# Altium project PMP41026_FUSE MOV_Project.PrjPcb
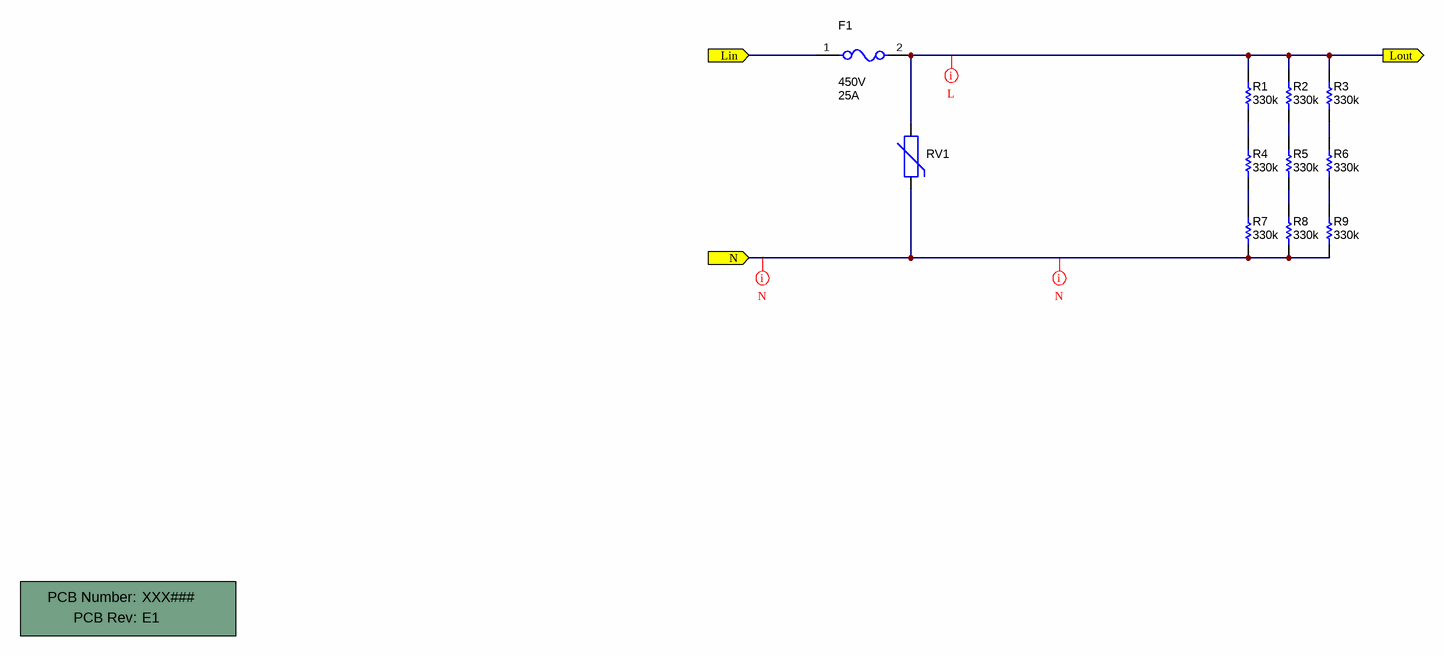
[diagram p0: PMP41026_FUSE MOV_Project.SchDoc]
CopyrightYear: 2018; PCB_Layout: Who did the Layout?; PCB_Rev: E1; PRJ_Customer: Public Release; PRJ_Engineer: Enter name of project lead; PRJ_Number: XXX###; PRJ_Title: Change in menu Project|Project Options|Parameters; SCH_Rev: E1; TechSupport: http://www.ti.com/support; TID: N/A
1 sheet, 12 parts. Net scope: flat (ports and power ports of the same name join across sheets).
Board file: PMP41026_FUSE MOV_Project.PcbDoc

## Sheet PMP41026_FUSE MOV_Project.SchDoc
size 431 x 279 mm; Date: Not shown in title block; ApprovedBy: Not shown in title block; CheckedBy: Not shown in title block; Author: Not shown in title block; CompanyName: Not shown in title block; Engineer: Not shown in title block; Organization: Not shown in title block; Address1: Not shown in title block; Address2: Not shown in title block; Address3: Not shown in title block; Address4: Not shown in title block; DocumentNumber: 1; Revision: Use project parameter SCH_Rev; SheetNumber: 1; SheetTotal: 3; PageSetup: Record=PageOptions¦CenterHorizontal=True¦CenterVertical=True¦PrintScale=1.00¦XCorrection=1.00¦YCorrection=1.00¦PrintKind=0¦BorderSize=5000000¦LeftOffset=0¦BottomOffset=0¦Orientation=2¦PaperLength=1000¦PaperWidth=1000¦Scale=100¦PaperSource=15¦PrintQuality=600¦MediaType=1¦DitherType=10¦PaperKind=Letter¦PrintScaleMode=1

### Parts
!PCB1  Printed Circuit Board  (value not drawn)  (mechanical)
F1  VDC_V: 450V  Fuse Current: 25A  [FP-0525025.MXEP_vm_AXIAL-MFG]  (hidden comment: 0525025.MXEP_vm)
R1  ValueDisplayed: 330k  [1206]  (hidden comment: CRCW1206330KJNEA)
R2  ValueDisplayed: 330k  [1206]  (hidden comment: CRCW1206330KJNEA)
R3  ValueDisplayed: 330k  [1206]  (hidden comment: CRCW1206330KJNEA)
R4  ValueDisplayed: 330k  [1206]  (hidden comment: CRCW1206330KJNEA)
R5  ValueDisplayed: 330k  [1206]  (hidden comment: CRCW1206330KJNEA)
R6  ValueDisplayed: 330k  [1206]  (hidden comment: CRCW1206330KJNEA)
R7  ValueDisplayed: 330k  [1206]  (hidden comment: CRCW1206330KJNEA)
R8  ValueDisplayed: 330k  [1206]  (hidden comment: CRCW1206330KJNEA)
R9  ValueDisplayed: 330k  [1206]  (hidden comment: CRCW1206330KJNEA)
RV1  S10K275E2  [VAR_S10K275E2]  (value not drawn)

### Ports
Lin (in), Lout (out), N (in)

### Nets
Lin: F1.1 ; port Lin
Lout: F1.2 R1.2 R2.2 R3.2 RV1.1 ; port Lout
N: R7.1 R8.1 R9.1 RV1.2 ; port N
NetR1_1: R1.1 R4.2
NetR2_1: R2.1 R5.2
NetR3_1: R3.1 R6.2
NetR4_1: R4.1 R7.2
NetR5_1: R5.1 R8.2
NetR6_1: R6.1 R9.2

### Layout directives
net class L: Lout, N
net class N: N

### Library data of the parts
!PCB1 = CMP-0003618-2: Manufacturer: Any; PartNumber: XXX###
F1 = CMP-4956-0000-1: 25A AC 450V DC Fuse Cartridge, Ceramic Through Hole 3AB, 3AG, 1/4" x 1-1/4" (Axial); Manufacturer: Littelfuse; AEC Grade: NA; Fuse Interrupt Dc Current: 10000A; AEC Qualified: No; Res_ohm: 3.8mΩ; MeltingTyp: 320A2Sec; Interrupt_DC: 10kA
R1-R9 = CMP-0018656-3: RES, 330 k, 5%, 0.25 W, AEC-Q200 Grade 0, 1206; Manufacturer: Vishay-Dale; Value: 330k; Power_W: 250mW; Value2: 0.25W; VDC_V: 200V; TempCo: 200 ppm/C; SizeArea_mm2: 5.12; SizeX_mm: 3.2; SizeY_mm: 1.6; SizeZ_mm: 1.35; EIA_Code: E24; AEC Category: Q200; AEC Qualified: Y; AEC Grade: 0
RV1 = CMP-0002100-2: Varistor 275V RMS 10MM Radial, TH; Manufacturer: TDK; SizeArea_mm2: 64.8; SizeAreaWB_mm2: 103.6; SizeX_mm: 12; SizeY_mm: 5.4; SizeZ_mm: 14.5

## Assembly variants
001: not fitted FID1 FID2 FID3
